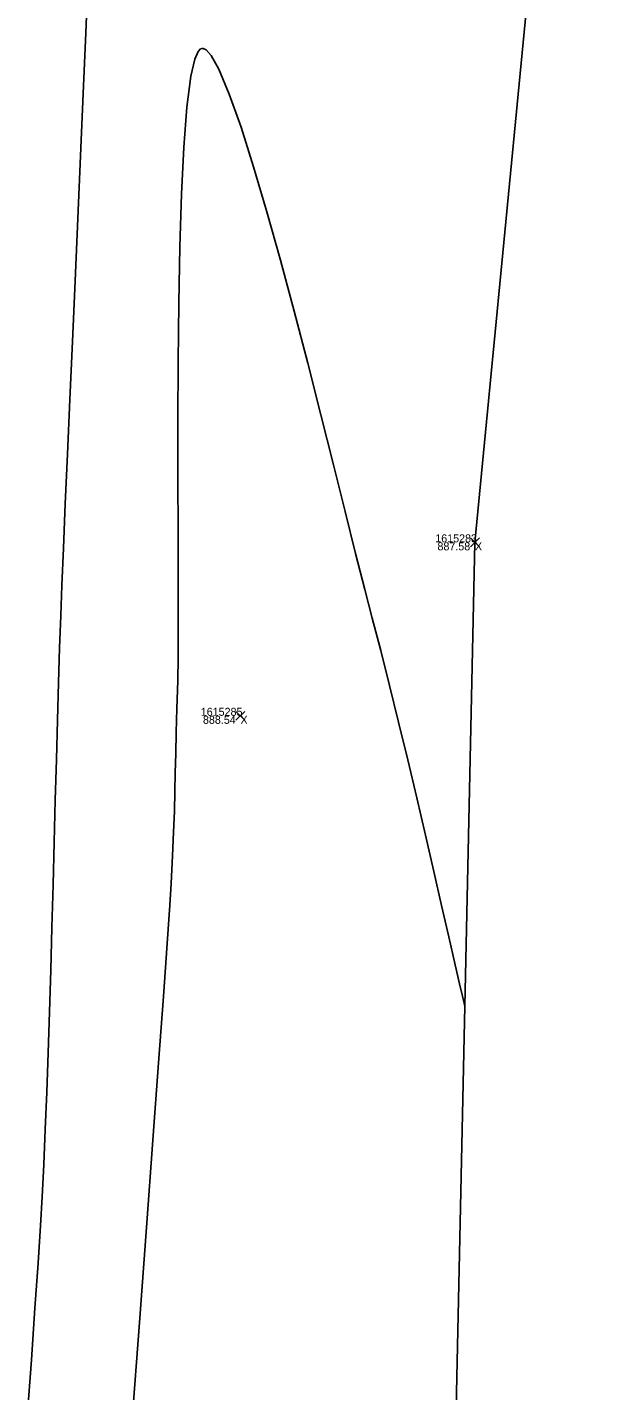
# Model space of a CAD drawing. Extents: x 1957117 to 1971063, y 701601 to 715861.
# Drawn here: x 1962752.3 to 1962778, y 702568.4 to 702628.1 of the extents above; entities that cross this region are included whole.
import ezdxf

# ---------------------------------------------------------------- set-up
doc = ezdxf.new("R2010")
doc.units = 0
for name, color, linetype in [('AP_X_Lights', 7, 'Continuous'), ('DT_X_Contour_Minor', 7, 'Continuous'), ('DT_X_TIN_Hull', 7, 'Continuous'), ('PV_P_Shoulder', 7, 'Continuous'), ('RS_Raster1', 7, 'Continuous'), ('SC_Scratch1', 7, 'Continuous')]:
    doc.layers.add(name, color=color, linetype=linetype)

msp = doc.modelspace()

# ---------------------------------------------------------------- linework, layer by layer
at = {"layer": 'AP_X_Lights'}
for p, q in [((1962771.653, 702605.35), (1962772.041, 702605.74)), ((1962771.653, 702605.74), (1962772.041, 702605.35)), ((1962761.406, 702597.762), (1962761.794, 702598.152)), ((1962761.406, 702598.152), (1962761.794, 702597.762))]:
    msp.add_line(p, q, dxfattribs=at)
at = {"layer": 'DT_X_Contour_Minor'}
for points in [[(1962752.287, 702567.281), (1962752.465, 702569.786), (1962752.622, 702572.046), (1962752.755, 702574.018), (1962752.859, 702575.657), (1962752.933, 702576.92), (1962753.003, 702578.33), (1962753.07, 702579.862), (1962753.134, 702581.497), (1962753.194, 702583.217), (1962753.252, 702585.003), (1962753.308, 702586.835), (1962753.361, 702588.696), (1962753.413, 702590.566), (1962753.463, 702592.427), (1962753.511, 702594.26), (1962753.559, 702596.046), (1962753.606, 702597.767), (1962753.653, 702599.403), (1962753.7, 702600.936), (1962753.747, 702602.348), (1962753.796, 702603.652), (1962753.864, 702605.293), (1962753.946, 702607.227), (1962754.042, 702609.409), (1962754.147, 702611.793), (1962754.26, 702614.334), (1962754.377, 702616.988), (1962754.497, 702619.709), (1962754.616, 702622.453), (1962754.731, 702625.173), (1962754.841, 702627.827), (1962754.941, 702630.367)], [(1962752.287, 702567.281), (1962752.465, 702569.786), (1962752.622, 702572.046), (1962752.755, 702574.018), (1962752.859, 702575.657), (1962752.933, 702576.92), (1962753.003, 702578.33), (1962753.07, 702579.862), (1962753.134, 702581.497), (1962753.194, 702583.217), (1962753.252, 702585.003), (1962753.308, 702586.835), (1962753.361, 702588.696), (1962753.413, 702590.566), (1962753.463, 702592.427), (1962753.511, 702594.26), (1962753.559, 702596.046), (1962753.606, 702597.767), (1962753.653, 702599.403), (1962753.7, 702600.936), (1962753.747, 702602.348), (1962753.796, 702603.652), (1962753.864, 702605.293), (1962753.946, 702607.227), (1962754.042, 702609.409), (1962754.147, 702611.793), (1962754.26, 702614.334), (1962754.377, 702616.988), (1962754.497, 702619.709), (1962754.616, 702622.453), (1962754.731, 702625.173), (1962754.841, 702627.827), (1962754.941, 702630.367)], [(1962771.408, 702585.243), (1962771.375, 702585.384), (1962771.302, 702585.695), (1962771.177, 702586.232), (1962770.985, 702587.069), (1962770.707, 702588.283), (1962770.393, 702589.655), (1962770.05, 702591.149), (1962769.685, 702592.733), (1962769.302, 702594.373), (1962768.91, 702596.034), (1962768.513, 702597.683), (1962768.119, 702599.288), (1962767.734, 702600.813), (1962767.363, 702602.225), (1962767.035, 702603.482), (1962766.635, 702605.061), (1962766.175, 702606.901), (1962765.665, 702608.941), (1962765.116, 702611.12), (1962764.539, 702613.377), (1962763.946, 702615.652), (1962763.347, 702617.882), (1962762.753, 702620.009), (1962762.176, 702621.969), (1962761.625, 702623.703), (1962761.114, 702625.15), (1962760.651, 702626.248), (1962760.324, 702626.835), (1962760.107, 702627.084), (1962759.977, 702627.152), (1962759.918, 702627.155), (1962759.86, 702627.135), (1962759.752, 702627.024), (1962759.604, 702626.684), (1962759.434, 702625.937), (1962759.261, 702624.585), (1962759.126, 702622.839), (1962759.026, 702620.776), (1962758.955, 702618.471), (1962758.909, 702616.002), (1962758.883, 702613.445), (1962758.872, 702610.876), (1962758.871, 702608.372), (1962758.877, 702606.008), (1962758.883, 702603.861), (1962758.885, 702602.009), (1962758.879, 702600.526), (1962758.86, 702599.489), (1962758.82, 702598.277), (1962758.792, 702597.234), (1962758.772, 702596.312), (1962758.754, 702595.463), (1962758.736, 702594.639), (1962758.713, 702593.79), (1962758.681, 702592.869), (1962758.637, 702591.827), (1962758.576, 702590.616), (1962758.516, 702589.667), (1962758.4, 702587.995), (1962758.234, 702585.674), (1962758.024, 702582.781), (1962757.775, 702579.39), (1962757.493, 702575.578), (1962757.183, 702571.418), (1962756.852, 702566.987)], [(1962771.408, 702585.243), (1962771.375, 702585.384), (1962771.302, 702585.695), (1962771.177, 702586.232), (1962770.985, 702587.069), (1962770.707, 702588.283), (1962770.393, 702589.655), (1962770.05, 702591.149), (1962769.685, 702592.733), (1962769.302, 702594.373), (1962768.91, 702596.034), (1962768.513, 702597.683), (1962768.119, 702599.288), (1962767.734, 702600.813), (1962767.363, 702602.225), (1962767.035, 702603.482), (1962766.635, 702605.061), (1962766.175, 702606.901), (1962765.665, 702608.941), (1962765.116, 702611.12), (1962764.539, 702613.377), (1962763.946, 702615.652), (1962763.347, 702617.882), (1962762.753, 702620.009), (1962762.176, 702621.969), (1962761.625, 702623.703), (1962761.114, 702625.15), (1962760.651, 702626.248), (1962760.324, 702626.835), (1962760.107, 702627.084), (1962759.977, 702627.152), (1962759.918, 702627.155), (1962759.86, 702627.135), (1962759.752, 702627.024), (1962759.604, 702626.684), (1962759.434, 702625.937), (1962759.261, 702624.585), (1962759.126, 702622.839), (1962759.026, 702620.776), (1962758.955, 702618.471), (1962758.909, 702616.002), (1962758.883, 702613.445), (1962758.872, 702610.876), (1962758.871, 702608.372), (1962758.877, 702606.008), (1962758.883, 702603.861), (1962758.885, 702602.009), (1962758.879, 702600.526), (1962758.86, 702599.489), (1962758.82, 702598.277), (1962758.792, 702597.234), (1962758.772, 702596.312), (1962758.754, 702595.463), (1962758.736, 702594.639), (1962758.713, 702593.79), (1962758.681, 702592.869), (1962758.637, 702591.827), (1962758.576, 702590.616), (1962758.516, 702589.667), (1962758.4, 702587.995), (1962758.234, 702585.674), (1962758.024, 702582.781), (1962757.775, 702579.39), (1962757.493, 702575.578), (1962757.183, 702571.418), (1962756.852, 702566.987)]]:
    msp.add_lwpolyline(points, dxfattribs=at)
at = {"layer": 'DT_X_TIN_Hull'}
msp.add_lwpolyline([(1962757.576, 702251.621), (1962759.026, 702351.713), (1962754.137, 702402.367), (1962769.625, 702502.771), (1962771.847, 702605.545), (1962775.888, 702647.495), (1962778.042, 702697.695)], dxfattribs=at)

# ---------------------------------------------------------------- texts
at = {"layer": 'PV_P_Shoulder'}
for s, p in [('887.58', (1962770.21, 702605.195)), ('888.54', (1962759.963, 702597.607))]:
    msp.add_text(s, height=0.35, dxfattribs=at).set_placement(p)
at = {"layer": 'RS_Raster1'}
for s, p in [('1615283', (1962770.114, 702605.545)), ('1615285', (1962759.867, 702597.957))]:
    msp.add_text(s, height=0.35, dxfattribs=at).set_placement(p)
at = {"layer": 'SC_Scratch1'}
for p in [(1962771.847, 702605.195), (1962761.6, 702597.607)]:
    msp.add_text('X', height=0.35, dxfattribs=at).set_placement(p)

doc.saveas('drawing.dxf')
